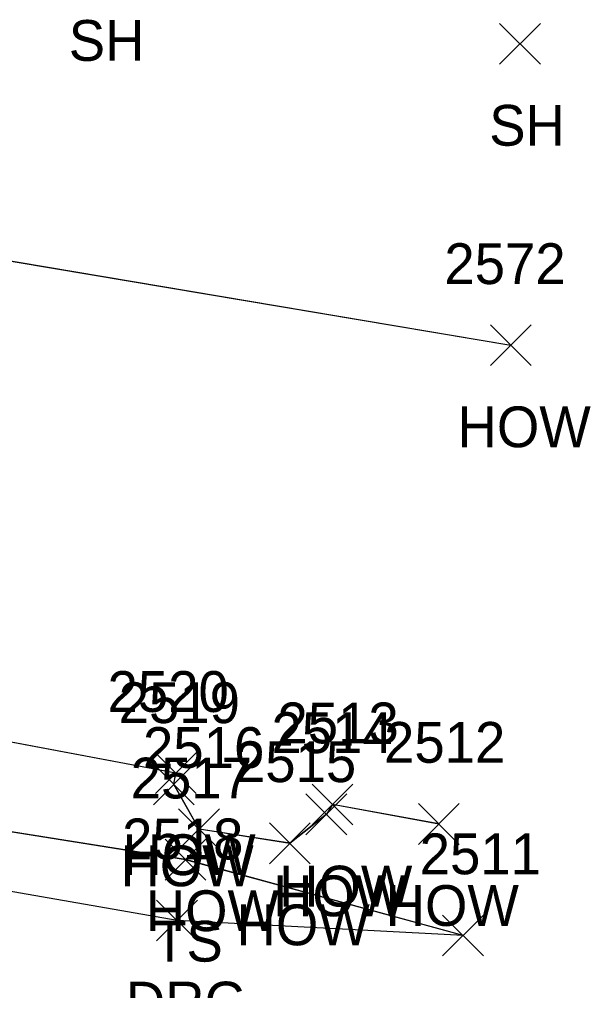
# Model space of a CAD drawing. Extents: x 1554668 to 1563881, y 831386 to 834374.
# Drawn here: x 1562253.72 to 1562281.74, y 832352.02 to 832399.64 of the extents above; entities that cross this region are included whole.
import ezdxf

# ---------------------------------------------------------------- set-up
doc = ezdxf.new("R2010")
doc.units = 0
for name, color, linetype in [('L_A', 7, 'Continuous'), ('L_I', 7, 'Continuous'), ('L_TIC', 7, 'Continuous'), ('LBC', 7, 'Continuous'), ('LELB', 7, 'Continuous'), ('R_A', 7, 'Continuous'), ('R_I', 7, 'Continuous'), ('R_TIC', 7, 'Continuous'), ('RDG', 7, 'Continuous')]:
    doc.layers.add(name, color=color, linetype=linetype)

msp = doc.modelspace()

# ---------------------------------------------------------------- linework, layer by layer
at = {"layer": 'L_TIC'}
for points in [[(1562277.279, 832397.444), (1562279.279, 832399.444)], [(1562279.279, 832397.444), (1562277.279, 832399.444)], [(1562276.828, 832382.66), (1562278.828, 832384.66)], [(1562278.828, 832382.66), (1562276.828, 832384.66)], [(1562260.391, 832361.681), (1562262.391, 832363.681)], [(1562262.391, 832361.681), (1562260.391, 832363.681)], [(1562260.293, 832361.134), (1562262.293, 832363.134)], [(1562262.293, 832361.134), (1562260.293, 832363.134)], [(1562268.076, 832360.141), (1562270.076, 832362.141)], [(1562270.076, 832360.141), (1562268.076, 832362.141)], [(1562267.779, 832359.663), (1562269.779, 832361.663)], [(1562269.779, 832359.663), (1562267.779, 832361.663)], [(1562273.301, 832359.189), (1562275.301, 832361.189)], [(1562275.301, 832359.189), (1562273.301, 832361.189)], [(1562261.533, 832358.935), (1562263.533, 832360.935)], [(1562263.533, 832358.935), (1562261.533, 832360.935)], [(1562265.988, 832358.24), (1562267.988, 832360.24)], [(1562267.988, 832358.24), (1562265.988, 832360.24)], [(1562260.873, 832357.439), (1562262.873, 832359.439)], [(1562262.873, 832357.439), (1562260.873, 832359.439)], [(1562274.484, 832353.722), (1562276.484, 832355.722)], [(1562276.484, 832353.722), (1562274.484, 832355.722)]]:
    msp.add_lwpolyline(points, dxfattribs=at)
at = {"layer": 'LBC'}
for points in [[(1562274.301, 832360.189), (1562269.076, 832361.141), (1562268.779, 832360.663), (1562266.988, 832359.24), (1562262.533, 832359.935), (1562261.293, 832362.134), (1562261.391, 832362.681), (1562243.482, 832366.044), (1562243.445, 832366.696), (1562247.586, 832388.664), (1562247.847, 832388.707), (1562277.828, 832383.66)], [(1562274.304, 832360.186), (1562269.078, 832361.135), (1562268.782, 832360.66), (1562266.99, 832359.233), (1562262.538, 832359.935), (1562261.296, 832362.127), (1562261.394, 832362.678), (1562243.485, 832366.04), (1562243.448, 832366.695), (1562247.59, 832388.659), (1562247.85, 832388.705), (1562277.831, 832383.658)], [(1562274.304, 832360.186), (1562269.078, 832361.135), (1562268.782, 832360.66), (1562266.99, 832359.233), (1562262.538, 832359.935), (1562261.296, 832362.127), (1562261.394, 832362.678), (1562243.485, 832366.04), (1562243.448, 832366.695), (1562247.59, 832388.659), (1562247.85, 832388.705), (1562277.831, 832383.658)], [(1562274.304, 832360.186), (1562269.078, 832361.135), (1562268.782, 832360.66), (1562266.99, 832359.233), (1562262.538, 832359.935), (1562261.296, 832362.127), (1562261.394, 832362.678), (1562243.485, 832366.04), (1562243.448, 832366.695), (1562247.59, 832388.659), (1562247.85, 832388.705), (1562277.831, 832383.658)]]:
    msp.add_lwpolyline(points, dxfattribs=at)
at = {"layer": 'LELB'}
for points in [[(1562275.484, 832354.722), (1562261.873, 832358.439), (1562242.505, 832361.523)], [(1562275.488, 832354.721), (1562261.876, 832358.436), (1562242.508, 832361.519)], [(1562275.488, 832354.721), (1562261.876, 832358.436), (1562242.508, 832361.519)], [(1562275.488, 832354.721), (1562261.876, 832358.436), (1562242.508, 832361.519)]]:
    msp.add_lwpolyline(points, dxfattribs=at)
at = {"layer": 'R_TIC'}
for points in [[(1562260.454, 832354.454), (1562262.454, 832356.454)], [(1562262.454, 832354.454), (1562260.454, 832356.454)], [(1562274.484, 832353.722), (1562276.484, 832355.722)], [(1562276.484, 832353.722), (1562274.484, 832355.722)]]:
    msp.add_lwpolyline(points, dxfattribs=at)
at = {"layer": 'RDG'}
for points in [[(1562275.484, 832354.722), (1562261.454, 832355.454), (1562241.858, 832358.865), (1562226.271, 832361.562), (1562222.837, 832363.343)], [(1562275.488, 832354.721), (1562261.457, 832355.449), (1562241.862, 832358.867), (1562226.274, 832361.558), (1562222.84, 832363.34)], [(1562275.488, 832354.721), (1562261.457, 832355.449), (1562241.862, 832358.867), (1562226.274, 832361.558), (1562222.84, 832363.34)], [(1562275.488, 832354.721), (1562261.457, 832355.449), (1562241.862, 832358.867), (1562226.274, 832361.558), (1562222.84, 832363.34)]]:
    msp.add_lwpolyline(points, dxfattribs=at)

# ---------------------------------------------------------------- texts
at = {"layer": 'L_A'}
for s, p in [('SH', (1562256.143, 832397.606)), ('SH', (1562276.768, 832393.444)), ('HOW', (1562275.214, 832378.66)), ('HOW', (1562258.777, 832357.681)), ('HOW', (1562258.679, 832357.134)), ('HOW', (1562266.462, 832356.141)), ('HOW', (1562266.165, 832355.663)), ('HOW', (1562271.687, 832355.189)), ('HOW', (1562259.919, 832354.935)), ('HOW', (1562264.374, 832354.24)), ('TS', (1562260.283, 832353.439))]:
    msp.add_text(s, height=2, dxfattribs=at).set_placement(p)
at = {"layer": 'L_I'}
for s, p in [('2572', (1562274.568, 832386.66)), ('2520', (1562258.044, 832365.681)), ('2519', (1562258.592, 832365.134)), ('2513', (1562266.383, 832364.141)), ('2514', (1562266.086, 832363.663)), ('2516', (1562259.785, 832362.935)), ('2512', (1562271.608, 832363.189)), ('2515', (1562264.295, 832362.24)), ('2517', (1562259.181, 832361.439)), ('2511', (1562273.358, 832357.722))]:
    msp.add_text(s, height=2, dxfattribs=at).set_placement(p)
at = {"layer": 'R_A'}
msp.add_text('DRG', height=2, dxfattribs=at).set_placement((1562258.942, 832350.454))
at = {"layer": 'R_I'}
for s, p in [('2518', (1562258.761, 832358.454)), ('2511', (1562273.358, 832357.722))]:
    msp.add_text(s, height=2, dxfattribs=at).set_placement(p)

doc.saveas('drawing.dxf')
